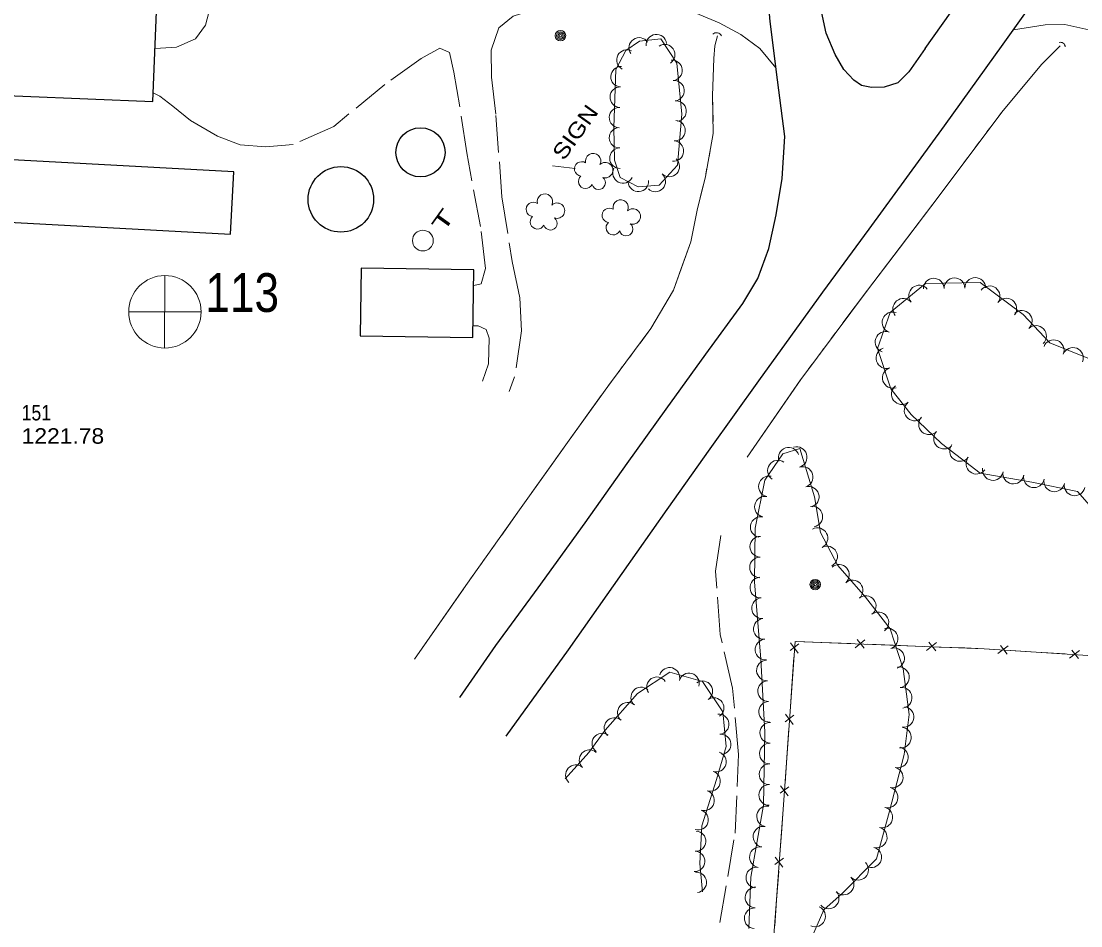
# Model space of a CAD drawing. Extents: x 299311 to 301657, y 49513 to 51866.
# Drawn here: x 300099.8 to 300509.3, y 50033.9 to 50383.5 of the extents above; entities that cross this region are included whole.
import ezdxf

# ---------------------------------------------------------------- set-up
doc = ezdxf.new("R2010")
doc.units = 0
doc.header["$LTSCALE"] = 2.4
doc.linetypes.add('LONG_DASHED', pattern=[7.5, 6, -1.5])
for name, color, linetype, lineweight in [('11', 7, 'Continuous', 25), ('12', 7, 'Continuous', 25), ('14', 7, 'Continuous', 13), ('15', 7, 'Continuous', 13), ('17', 7, 'LONG_DASHED', 13), ('18', 7, 'Continuous', 13), ('19', 7, 'Continuous', 13), ('4', 7, 'Continuous', 13), ('6', 7, 'Continuous', 13)]:
    doc.layers.add(name, color=color, linetype=linetype, lineweight=lineweight)

msp = doc.modelspace()

# ---------------------------------------------------------------- linework, layer by layer
at = {"layer": '11'}
for points in [[(300449.171, 50372.95), (300462.402, 50391.823), (300478.238, 50414.348), (300497.847, 50441.838), (300516.893, 50468.271), (300538.883, 50498.768), (300558.362, 50525.367), (300577.633, 50552.405), (300598.2, 50580.809), (300618.37, 50608.824), (300640.297, 50638.797)], [(300287.176, 50107.164), (300311.291, 50140.598), (300331.977, 50169.98), (300349.427, 50194.729), (300366.089, 50218.225), (300384.892, 50244.576), (300409.609, 50278.747), (300427.494, 50303.203), (300456.56, 50343.148), (300479.329, 50374.693), (300497.325, 50400.091), (300518.311, 50429.548), (300539.854, 50459.658), (300560.519, 50488.121), (300581.893, 50517.65), (300601.128, 50544.137), (300623.029, 50574.5), (300642.077, 50601.015), (300659.645, 50625.084)], [(300269.259, 50122.088), (300283.213, 50142.149), (300299.569, 50164.511), (300317.787, 50189.652), (300334.031, 50212.576), (300349.003, 50233.575), (300364.401, 50254.769), (300378.702, 50274.374), (300384.509, 50284.011), (300388.686, 50295.607), (300391.506, 50308.722), (300393.874, 50322.709), (300394.896, 50338.981), (300392.037, 50360.801), (300389.239, 50383.352), (300386.478, 50414.413), (300385.011, 50441.691), (300384.56, 50468.923), (300384.731, 50500.04), (300383.99, 50528.88), (300384.149, 50554.459), (300383.961, 50584.641), (300383.895, 50619.722)], [(300449.171, 50372.95), (300442.828, 50363.946), (300438.55, 50359.732), (300433.231, 50358.033), (300428.416, 50357.856), (300424.537, 50358.691), (300421.532, 50360.789), (300417.686, 50364.881), (300414.413, 50370.655), (300410.92, 50378.945), (300407.555, 50394.652), (300404.294, 50429.226), (300403.819, 50454.543), (300404.115, 50484.571), (300403.976, 50504.923), (300403.289, 50531.909), (300403.127, 50563.445), (300403.577, 50587.789), (300403.079, 50614.351)]]:
    msp.add_lwpolyline(points, dxfattribs=at)
at = {"layer": '12'}
for points in [[(300075.204, 50355.583), (300150.684, 50352.453), (300152.523, 50396.811), (300143.36, 50397.191), (300143.912, 50410.516), (300134.414, 50410.91), (300135.256, 50431.215), (300151.36, 50430.548), (300151.947, 50444.691), (300136.039, 50445.35), (300136.945, 50467.2), (300079.901, 50469.565), (300077.032, 50400.381), (300077.062, 50400.38)], [(300092.717, 50305.97), (300180.635, 50301.154), (300181.955, 50325.26), (300094.037, 50330.076)], [(300274.779, 50287.374), (300231.156, 50288.049), (300230.752, 50261.959), (300274.375, 50261.284)]]:
    msp.add_lwpolyline(points, close=True, dxfattribs=at)
for centre, radius in [((300254.092, 50332.839), 9.493), ((300223.325, 50314.645), 12.661)]:
    msp.add_circle(centre, radius, dxfattribs=at)
at = {"layer": '12', "lineweight": 13}
msp.add_circle((300255.019, 50298.73), 4.011, dxfattribs=at)
at = {"layer": '14'}
msp.add_line((300305.068, 50327.572), (300313.866, 50326.588), dxfattribs=at)
for centre, radius in [((300308.195, 50377.94), 2.018), ((300308.183, 50377.945), 1.518), ((300308.219, 50377.927), 1.008), ((300308.213, 50377.936), 0.502), ((300406.644, 50165.742), 2.018), ((300406.632, 50165.747), 1.518), ((300406.668, 50165.729), 1.008), ((300406.662, 50165.738), 0.502)]:
    msp.add_circle(centre, radius, dxfattribs=at)
at = {"layer": '15'}
for p, q in [((300400.26, 50142.808), (300396.927, 50140.258)), ((300397.064, 50143.2), (300400.015, 50139.296)), ((300409.192, 50143.353), (300399.315, 50143.729)), ((300420.421, 50142.925), (300409.192, 50143.353)), ((300425.865, 50144.445), (300422.056, 50141.373)), ((300425.574, 50141.239), (300422.92, 50144.49)), ((300436.826, 50142.3), (300426.95, 50142.677)), ((300453.5, 50143.393), (300449.69, 50140.321)), ((300453.209, 50140.187), (300450.555, 50143.438)), ((300448.056, 50141.873), (300436.826, 50142.3)), ((300464.461, 50141.248), (300454.585, 50141.624)), ((300481.167, 50142.099), (300477.279, 50139.127)), ((300480.793, 50138.902), (300478.225, 50142.221)), ((300492.069, 50139.67), (300482.205, 50140.303)), ((300503.283, 50138.95), (300492.069, 50139.67)), ((300508.765, 50140.327), (300504.877, 50137.355)), ((300508.39, 50137.13), (300505.822, 50140.449)), ((300398.412, 50137.711), (300397.63, 50126.501)), ((300397.63, 50126.501), (300396.942, 50116.641)), ((300398.336, 50115.22), (300395.003, 50112.671)), ((300395.14, 50115.612), (300398.091, 50111.708)), ((300396.488, 50110.123), (300395.706, 50098.913)), ((300395.706, 50098.913), (300395.018, 50089.053)), ((300396.412, 50087.633), (300393.079, 50085.083)), ((300393.216, 50088.025), (300396.167, 50084.12)), ((300393.757, 50071.327), (300393.027, 50061.471)), ((300394.414, 50060.044), (300391.07, 50057.509)), ((300391.22, 50060.45), (300394.154, 50056.533)), ((300392.544, 50054.955), (300391.714, 50043.748)), ((300391.714, 50043.748), (300390.984, 50033.891))]:
    msp.add_line(p, q, dxfattribs=at)
for points in [[(300825.105, 50257.815), (300812.538, 50222.335), (300764.322, 50225.321), (300715.715, 50226.496), (300671.678, 50227.929), (300567.676, 50228.641), (300558.07, 50135.432), (300471.877, 50140.966), (300398.833, 50143.747), (300394.186, 50077.12), (300389.671, 50016.169)], [(300475.685, 50140.721), (300471.877, 50140.966), (300464.461, 50141.248)], [(300394.564, 50082.536), (300394.186, 50077.12), (300393.757, 50071.327)]]:
    msp.add_lwpolyline(points, dxfattribs=at)
for centre, radius, start, end in [((300368.506, 50376.926), 2.148, 27.12649, 133.36605), ((300501.429, 50373.559), 1.819, 1.37608, 107.61564)]:
    msp.add_arc(centre, radius, start, end, dxfattribs=at)
at = {"layer": '17'}
for points in [[(300151.534, 50372.964), (300159.803, 50373.485), (300167.09, 50376.697), (300171.057, 50382.007), (300173.442, 50391.22), (300172.447, 50398.873), (300168.434, 50402.595), (300163.742, 50406.624), (300159.944, 50409.807), (300154.601, 50413.244), (300148.266, 50414.175), (300134.542, 50413.988)], [(300391.448, 50365.545), (300385.301, 50372.924), (300377.884, 50378.354), (300369.581, 50382.944), (300358.66, 50387.471), (300340.613, 50390.152), (300322.022, 50390.254), (300302.879, 50389.645), (300289.98, 50385.488), (300284.399, 50380.961), (300281.379, 50372.308), (300281.527, 50361.869), (300283.227, 50347.108), (300285.594, 50315.666), (300289.573, 50290.615), (300292.477, 50276.643), (300293.16, 50263.815), (300290.486, 50246.073), (300288.337, 50240.446)], [(300483.26, 50380.24), (300495.509, 50382.187), (300503.125, 50382.224), (300513.523, 50379.935), (300536.672, 50372.41), (300565.475, 50363.31), (300599.051, 50352.904), (300616.281, 50347.907), (300623.501, 50345.537), (300629.991, 50342.574), (300634.341, 50337.408), (300635.297, 50328.904), (300634.879, 50324.791), (300632.563, 50311.884)], [(300274.686, 50281.359), (300277.555, 50282.025), (300279.265, 50287.934), (300277.25, 50304.136), (300272.004, 50332.634), (300269.325, 50350.372), (300267.007, 50363.853), (300265.25, 50371.439), (300261.606, 50373.1), (300254.371, 50369.073), (300240.356, 50359.09), (300220.59, 50342.839), (300204.936, 50335.901), (300194.379, 50334.924), (300184.385, 50335.759), (300175.638, 50339.125), (300165.211, 50345.139), (300158.404, 50350.704), (300153.363, 50354.603), (300150.822, 50355.782)], [(300278.023, 50244.439), (300280.446, 50251.14), (300280.634, 50260.958), (300279.495, 50264.356), (300276.411, 50265.734), (300274.445, 50265.79)], [(300369.814, 50035.168), (300375.682, 50069.711), (300376.964, 50100.093), (300374.738, 50125.749), (300369.942, 50146.47), (300368.133, 50170.961), (300370.154, 50184.786)]]:
    msp.add_lwpolyline(points, dxfattribs=at)
at = {"layer": '18'}
msp.add_lwpolyline([(300328.81, 50342.38), (300329.122, 50329.805), (300331.288, 50323.096), (300338.222, 50319.512), (300346.365, 50320.178), (300353.468, 50327.824), (300355.058, 50347.578), (300353.123, 50367.329), (300346.932, 50376.764), (300338.75, 50375.822), (300333.461, 50372.213), (300329.608, 50364.823)], close=True, dxfattribs=at)
for points in [[(300511.997, 50253.32), (300497.335, 50259.169), (300487.039, 50270.166), (300470.341, 50282.539), (300449.257, 50282.171), (300435.657, 50270.865), (300430.732, 50257.061), (300435.821, 50241.459), (300443.689, 50231.472), (300455.42, 50220.292), (300470.345, 50208.798), (300490.304, 50205.307), (300508.038, 50201.726), (300517.999, 50190.311)], [(300405.196, 50029.103), (300409.998, 50040.021), (300417.103, 50046.347), (300430.273, 50059.7), (300435.406, 50078.233), (300441.019, 50100.048), (300442.987, 50115.573), (300440.671, 50133.164), (300435.563, 50148.669), (300426.086, 50160.95), (300415.389, 50173.163), (300408.682, 50185.926), (300406.324, 50199.642), (300400.64, 50218.334), (300394.169, 50216.235), (300387.131, 50206.083), (300383.387, 50187.508), (300383.168, 50166.818), (300385.672, 50136.956), (300387.195, 50108.685), (300386.691, 50080.516), (300381.807, 50052.692), (300381.01, 50032.869)], [(300363.148, 50046.937), (300362.067, 50057.984), (300362.826, 50072.448), (300368.435, 50090.441), (300372.289, 50103.158), (300370.963, 50116.541), (300363.071, 50128.261), (300350.483, 50131.867), (300337.984, 50123.72), (300325.503, 50109.478), (300319.187, 50100.792), (300309.956, 50090.689)]]:
    msp.add_lwpolyline(points, dxfattribs=at)
for centre, radius, start, end in [((300338.604, 50373.215), 3.957, 34.31571, 214.30039), ((300345.268, 50374.488), 3.957, 6.57525, 186.55993), ((300333.864, 50368.508), 3.957, 62.47102, 242.45569), ((300348.491, 50370.613), 3.957, 303.2795, 123.26418), ((300351.318, 50364.514), 3.957, 275.60306, 95.58774), ((300331.582, 50362.074), 3.957, 87.97127, 267.95595), ((300352.09, 50356.639), 3.957, 275.60306, 95.58774), ((300331.301, 50354.167), 3.957, 87.97127, 267.95595), ((300352.861, 50348.765), 3.957, 275.60306, 95.58774), ((300331.02, 50346.26), 3.957, 87.97127, 267.95595), ((300352.471, 50341.248), 3.957, 265.40584, 85.39052), ((300330.978, 50338.476), 3.957, 91.42894, 271.41362), ((300351.836, 50333.362), 3.957, 265.40584, 85.39052), ((300320.817, 50329.465), 2.974, 332.7899, 194.02379), ((300331.175, 50330.566), 3.957, 91.42894, 271.41362), ((300316.369, 50326.449), 2.777, 55.76079, 263.53379), ((300325.509, 50325.965), 2.975, 250.44072, 133.41399), ((300350.234, 50327.385), 3.957, 227.11611, 47.10079), ((300317.935, 50321.636), 2.783, 132.43781, 333.44885), ((300322.945, 50321.074), 2.611, 195.14595, 53.07856), ((300332.374, 50324.866), 3.957, 152.67442, 332.6591), ((300344.848, 50321.588), 3.957, 227.11611, 47.10079), ((300338.311, 50321.597), 3.957, 184.68336, 4.66804), ((300302.17, 50313.794), 2.974, 332.7899, 194.02379), ((300297.722, 50310.778), 2.777, 55.76079, 263.53379), ((300306.862, 50310.294), 2.975, 250.44072, 133.41399), ((300327.019, 50308.531), 2.777, 55.76079, 263.53379), ((300331.467, 50311.547), 2.974, 332.7899, 194.02379), ((300336.159, 50308.047), 2.975, 250.44072, 133.41399), ((300299.288, 50305.965), 2.783, 132.43781, 333.44885), ((300304.298, 50305.403), 2.611, 195.14595, 53.07856), ((300328.585, 50303.718), 2.783, 132.43781, 333.44885), ((300333.595, 50303.156), 2.611, 195.14595, 53.07856), ((300452.45, 50280.126), 4.014, 1.0076, 180.99228), ((300460.475, 50280.266), 4.014, 1.0076, 180.99228), ((300468.5, 50280.406), 4.014, 1.0076, 180.99228), ((300446.855, 50277.443), 4.014, 39.74521, 219.72988), ((300474.03, 50277.191), 4.014, 323.4697, 143.45438), ((300440.684, 50272.312), 4.014, 39.74521, 219.72988), ((300480.479, 50272.413), 4.014, 323.4697, 143.45438), ((300436.548, 50267.112), 4.014, 70.37224, 250.35692), ((300486.474, 50267.696), 4.014, 313.12207, 133.10675), ((300491.96, 50261.837), 4.014, 313.12207, 133.10675), ((300433.851, 50259.552), 4.014, 70.37224, 250.35692), ((300498.791, 50256.327), 4.014, 338.2595, 158.24418), ((300506.245, 50253.353), 4.014, 338.2595, 158.24418), ((300434.165, 50253.309), 4.014, 108.07275, 288.05743), ((300436.654, 50245.679), 4.014, 108.07275, 288.05743), ((300440.115, 50239.403), 4.014, 128.23956, 308.22423), ((300445.082, 50233.098), 4.014, 128.23956, 308.22423), ((300450.648, 50227.742), 4.014, 136.38534, 316.37001), ((300456.458, 50222.205), 4.014, 136.38534, 316.37001), ((300396.383, 50214.75), 4.004, 17.97918, 197.96386), ((300399.465, 50214.995), 4.004, 286.92151, 106.90619), ((300462.611, 50217.406), 4.014, 142.40717, 322.39185), ((300392.268, 50209.814), 4.004, 55.27555, 235.26022), ((300468.97, 50212.509), 4.014, 142.40717, 322.39185), ((300401.794, 50207.334), 4.004, 286.92151, 106.90619), ((300475.309, 50210.062), 4.014, 170.0865, 350.07118), ((300483.215, 50208.679), 4.014, 170.0865, 350.07118), ((300388.787, 50203.694), 4.004, 78.61174, 258.59642), ((300491.173, 50207.275), 4.014, 168.59152, 348.5762), ((300499.041, 50205.686), 4.014, 168.59152, 348.5762), ((300506.908, 50204.097), 4.014, 168.59152, 348.5762), ((300404.124, 50199.673), 4.004, 286.92151, 106.90619), ((300387.205, 50195.844), 4.004, 78.61174, 258.59642), ((300405.502, 50192.055), 4.004, 279.76237, 99.74705), ((300385.623, 50187.994), 4.004, 78.61174, 258.59642), ((300407.491, 50183.686), 4.004, 297.72974, 117.71442), ((300385.408, 50180.397), 4.004, 89.40122, 269.3859), ((300411.217, 50176.598), 4.004, 297.72974, 117.71442), ((300385.323, 50172.389), 4.004, 89.40122, 269.3859), ((300415.806, 50169.505), 4.004, 311.22181, 131.20648), ((300385.458, 50164.588), 4.004, 94.80084, 274.78551), ((300421.083, 50163.482), 4.004, 311.22181, 131.20648), ((300386.127, 50156.608), 4.004, 94.80084, 274.78551), ((300426.141, 50157.448), 4.004, 307.66431, 127.64898), ((300431.034, 50151.108), 4.004, 307.66431, 127.64898), ((300386.796, 50148.628), 4.004, 94.80084, 274.78551), ((300434.608, 50144.87), 4.004, 288.24172, 108.2264), ((300387.466, 50140.649), 4.004, 94.80084, 274.78551), ((300437.114, 50137.264), 4.004, 288.24172, 108.2264), ((300388.006, 50132.597), 4.004, 93.09129, 273.07597), ((300350.371, 50129.767), 3.917, 344.0226, 164.00727), ((300357.901, 50127.609), 3.917, 344.0226, 164.00727), ((300438.985, 50129.916), 4.004, 277.50799, 97.49266), ((300345.434, 50126.129), 3.917, 33.10446, 213.08914), ((300363.07, 50124.592), 3.917, 303.96315, 123.94783), ((300388.436, 50124.601), 4.004, 93.09129, 273.07597), ((300339.343, 50122.16), 3.917, 48.77791, 228.76258), ((300440.03, 50121.977), 4.004, 277.50799, 97.49266), ((300334.18, 50116.269), 3.917, 48.77791, 228.76258), ((300367.446, 50118.094), 3.917, 303.96315, 123.94783), ((300388.867, 50116.605), 4.004, 93.09129, 273.07597), ((300440.748, 50114.574), 4.004, 262.78319, 82.76787), ((300329.017, 50110.377), 3.917, 48.77791, 228.76258), ((300369.374, 50111.78), 3.917, 275.66611, 95.65079), ((300389.287, 50108.458), 4.004, 88.98263, 268.96731), ((300439.741, 50106.63), 4.004, 262.78319, 82.76787), ((300324.314, 50104.357), 3.917, 53.98499, 233.96967), ((300370.147, 50103.985), 3.917, 275.66611, 95.65079), ((300319.395, 50097.98), 3.917, 47.59006, 227.57474), ((300389.144, 50100.452), 4.004, 88.98263, 268.96731), ((300438.581, 50098.983), 4.004, 255.57844, 75.56312), ((300368.355, 50097.245), 3.917, 253.14776, 73.13244), ((300314.111, 50092.197), 3.917, 47.59006, 227.57474), ((300366.077, 50089.767), 3.917, 252.69372, 72.67839), ((300389.001, 50092.446), 4.004, 88.98263, 268.96731), ((300436.585, 50091.228), 4.004, 255.57844, 75.56312), ((300363.746, 50082.288), 3.917, 252.69372, 72.67839), ((300388.857, 50084.439), 4.004, 88.98263, 268.96731), ((300434.59, 50083.473), 4.004, 255.57844, 75.56312), ((300361.415, 50074.81), 3.917, 252.69372, 72.67839), ((300388.056, 50076.168), 4.004, 80.05185, 260.03652), ((300432.549, 50075.769), 4.004, 254.52677, 74.51145), ((300360.464, 50066.565), 3.917, 267.00381, 86.98849), ((300386.671, 50068.281), 4.004, 80.05185, 260.03652), ((300430.412, 50068.052), 4.004, 254.52677, 74.51145), ((300360.054, 50058.742), 3.917, 267.00381, 86.98849), ((300385.287, 50060.394), 4.004, 80.05185, 260.03652), ((300428.274, 50060.335), 4.004, 254.52677, 74.51145), ((300423.213, 50055.526), 4.004, 225.40298, 45.38766), ((300360.726, 50050.636), 3.917, 275.59652, 95.5812), ((300383.902, 50052.507), 4.004, 80.05185, 260.03652), ((300417.59, 50049.825), 4.004, 225.40298, 45.38766), ((300383.587, 50044.786), 4.004, 87.70528, 267.68996), ((300411.833, 50044.461), 4.004, 221.68822, 41.67289), ((300383.265, 50036.785), 4.004, 87.70528, 267.68996), ((300406.596, 50037.492), 4.004, 246.26661, 66.25129)]:
    msp.add_arc(centre, radius, start, end, dxfattribs=at)
at = {"layer": '19'}
for p, q in [((300473.013, 50340.729), (300474.51, 50342.73)), ((300468.522, 50334.725), (300470.019, 50336.726)), ((300365.625, 50331.224), (300366.04, 50333.472)), ((300464.031, 50328.721), (300465.528, 50330.723)), ((300364.381, 50324.48), (300364.795, 50326.728)), ((300412.865, 50260.882), (300414.359, 50262.886)), ((300334.839, 50253.551), (300336.207, 50255.388)), ((300408.384, 50254.871), (300409.878, 50256.875)), ((300330.734, 50248.04), (300332.103, 50249.877)), ((300403.903, 50248.86), (300405.397, 50250.864)), ((300380.362, 50215.008), (300400.924, 50244.847)), ((300281.389, 50179.151), (300282.713, 50181.019)), ((300277.415, 50173.545), (300278.74, 50175.414)), ((300273.442, 50167.94), (300274.766, 50169.808)), ((300251.814, 50136.948), (300270.803, 50164.196))]:
    msp.add_line(p, q, dxfattribs=at)
for points in [[(300251.814, 50136.948), (300271.667, 50165.436), (300292.379, 50194.655), (300310.931, 50220.65), (300327.189, 50243.279), (300343.137, 50264.694), (300351.83, 50279.498), (300358.519, 50298.202), (300360.976, 50310.444), (300364.189, 50323.442), (300367.265, 50340.111), (300367.002, 50354.751), (300367.454, 50369.095), (300367.908, 50374.014), (300368.854, 50377.842)], [(300367.181, 50344.793), (300367.002, 50354.751), (300367.454, 50369.095), (300367.908, 50374.014), (300368.854, 50377.842)], [(300380.362, 50215.008), (300401.067, 50245.055), (300426.795, 50279.57), (300454.565, 50316.067), (300478.765, 50348.418), (300494.068, 50366.745), (300501.319, 50373.998)], [(300477.504, 50346.732), (300478.765, 50348.418), (300494.068, 50366.745), (300501.319, 50373.998)], [(300366.87, 50337.968), (300367.265, 50340.111), (300367.263, 50340.218)], [(300439.164, 50295.827), (300454.565, 50316.067), (300461.037, 50324.719)], [(300354.869, 50287.996), (300358.519, 50298.202), (300360.976, 50310.444), (300363.345, 50320.027)], [(300417.346, 50266.894), (300426.795, 50279.57), (300439.164, 50295.827)], [(300338.943, 50259.062), (300343.137, 50264.694), (300351.83, 50279.498), (300354.869, 50287.996)], [(300326.643, 50242.519), (300327.189, 50243.279), (300327.998, 50244.366)], [(300304.621, 50211.809), (300310.931, 50220.65), (300323.97, 50238.799)], [(300285.362, 50184.756), (300292.379, 50194.655), (300304.621, 50211.809)]]:
    msp.add_lwpolyline(points, dxfattribs=at)
at = {"layer": '4'}
for p, q in [((300155.285, 50285.229), (300155.22, 50257.375)), ((300141.376, 50271.199), (300169.281, 50271.186))]:
    msp.add_line(p, q, dxfattribs=at)
msp.add_circle((300155.337, 50271.207), 14, dxfattribs=at)

# ---------------------------------------------------------------- texts
at = {"layer": '12', "width": 1.7}
msp.add_text('T', height=6, rotation=54.366, dxfattribs=at).set_placement((300262.853, 50301.479))
at = {"layer": '14', "width": 1.2}
msp.add_text('SIGN', height=6, rotation=54.366, dxfattribs=at).set_placement((300309.475, 50329.302))
at = {"layer": '4', "width": 0.85}
msp.add_text('113', height=15, dxfattribs=at).set_placement((300170.989, 50271.137))
at = {"layer": '6'}
for s, width, p in [('151', 0.85, (300099.958, 50229.202)), ('1221.78', 1.1, (300099.958, 50220.202))]:
    msp.add_text(s, height=6, dxfattribs=dict(at, width=width)).set_placement(p)

doc.saveas('drawing.dxf')
